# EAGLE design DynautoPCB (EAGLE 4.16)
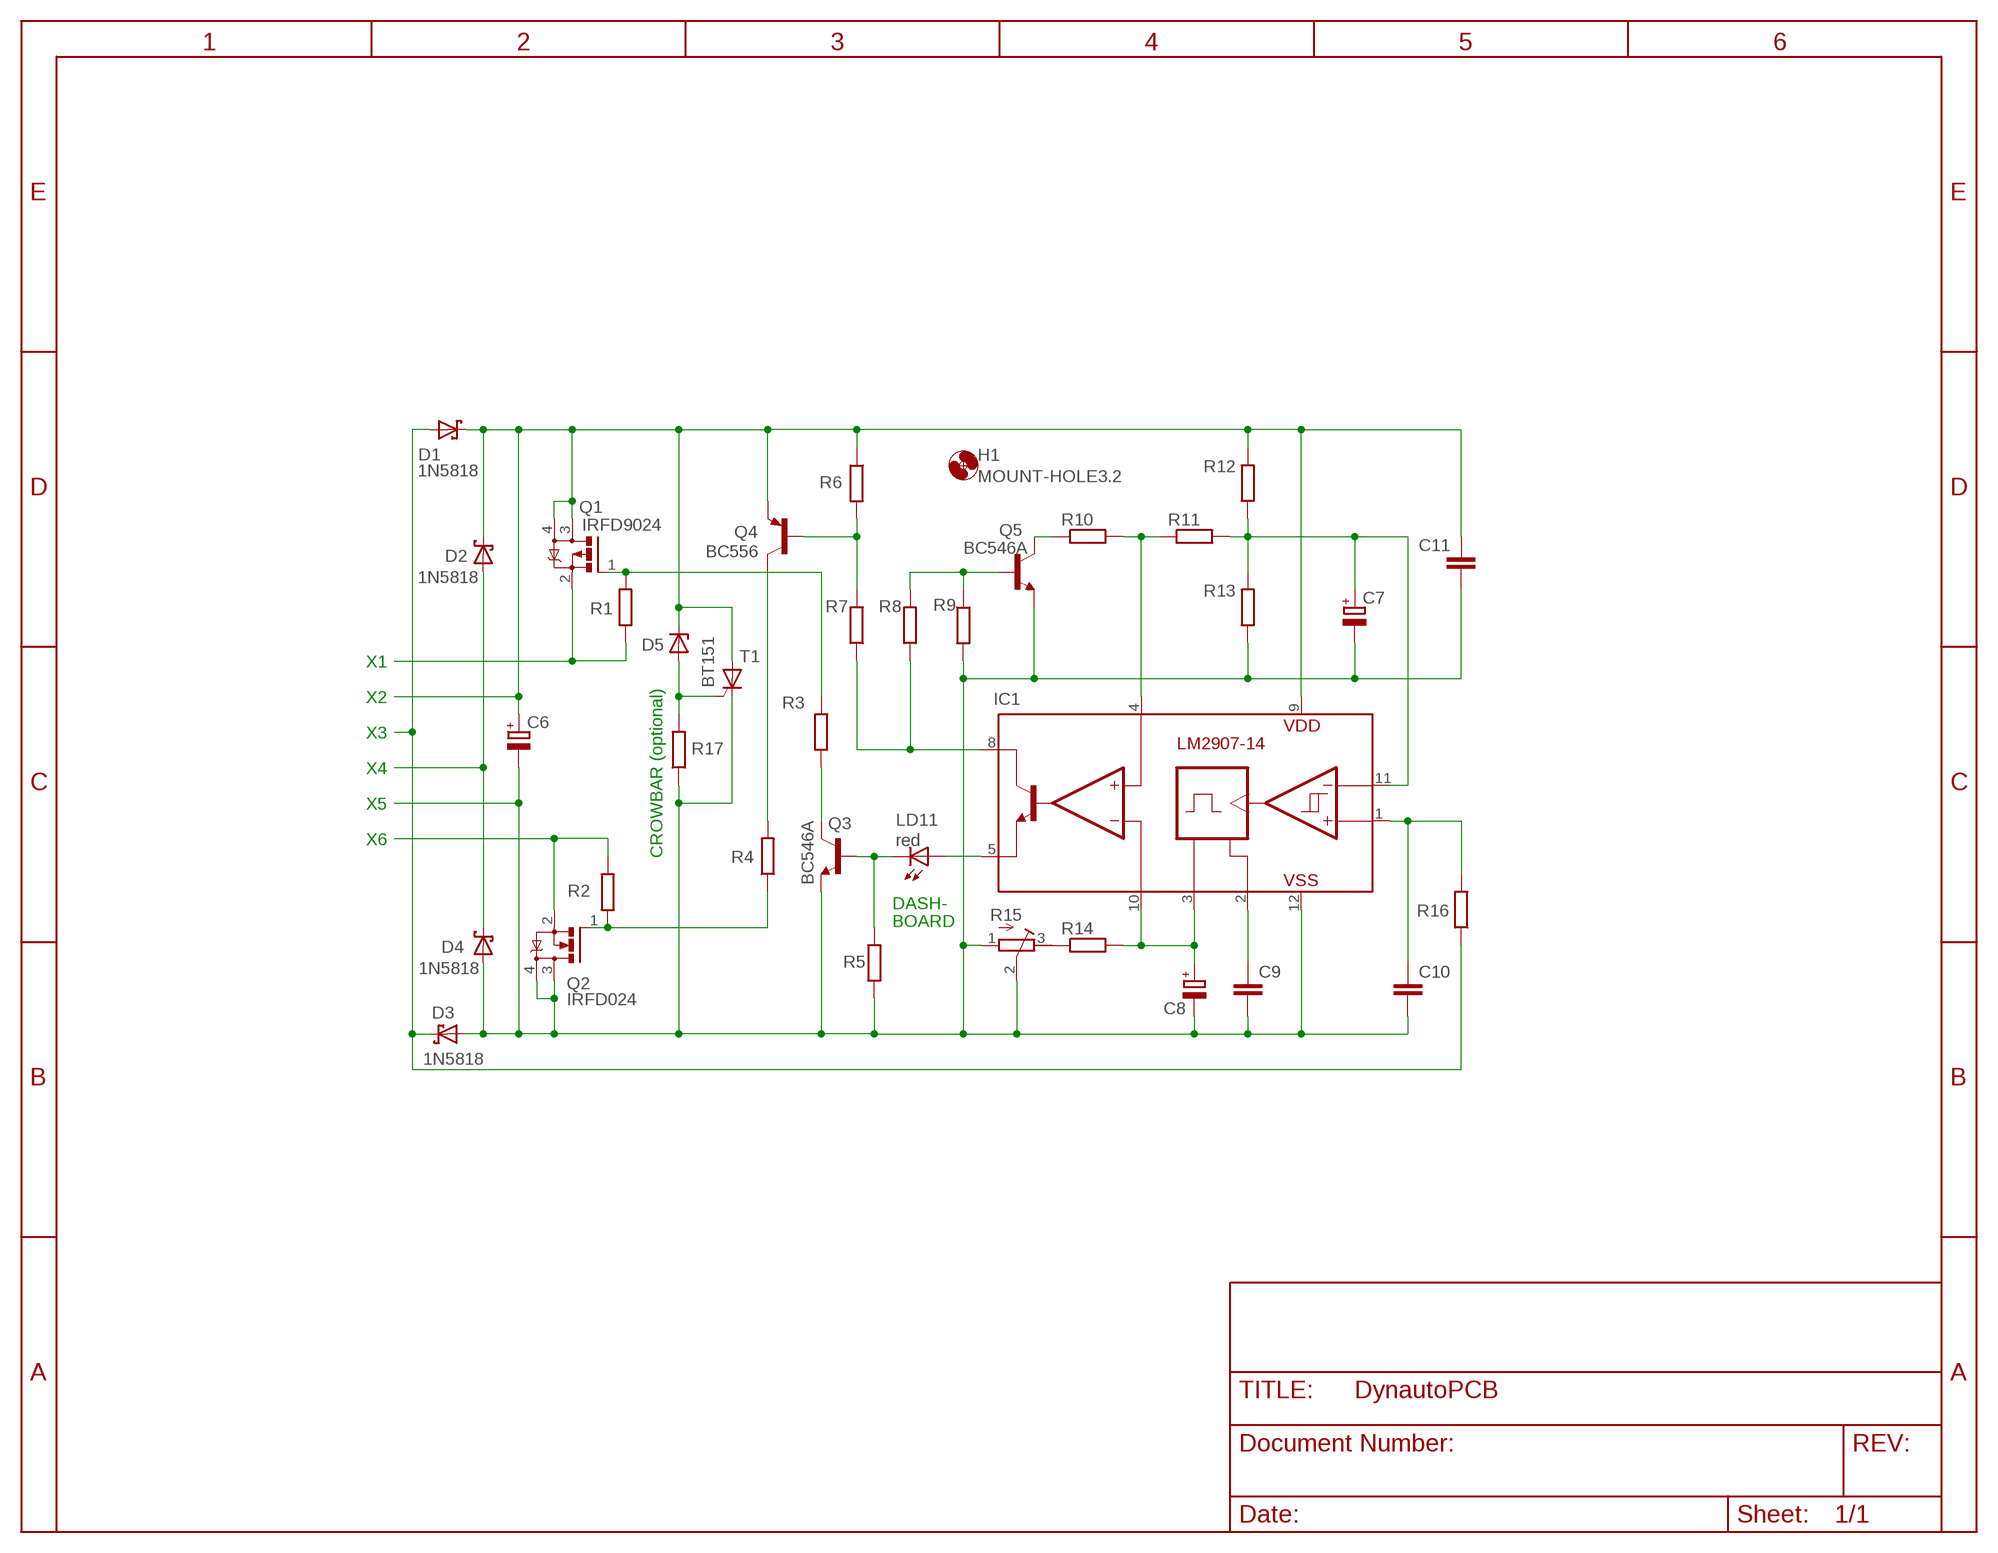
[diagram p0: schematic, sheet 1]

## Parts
C6  CPOL-EUTT5D2.5-10  [TT5D2.5-10]
C7  CPOL-EUE2.5-5  [E2,5-5]
C8  CPOL-EUE2.5-5  [E2,5-5]
C9  C-EU025_050-045X075  [C025_050-045X075]
C10  C-EU025_050-035X075  [C025_050-035X075]
C11  C-EU025_050-035X075  [C025_050-035X075]
D1  1N5818  1N5818H  [DO41-10]
D2  1N5818  1N5818H  [DO41-10]
D3  1N5818  1N5818H  [DO41-10]
D4  1N5818  1N5818H  [DO41-10]
D5  ZENER-DIODEDO34-7  [DO34Z7]
H1  MOUNT-HOLE3.2  [3,2]
IC1  LM2907-14N  [DIL14]
LD11  red  LEDV  [LED3MM]
Q1  IRFD9024  [DIL-8]
Q2  IRFD024  [DIL-8]
Q3  BC546A  [TO92-EBC]
Q4  BC556  [TO92-EBC]
Q5  BC546A  [TO92-EBC]
R1  R-EU_0204/2V  [0204V]
R2  R-EU_0204/2V  [0204V]
R3  R-EU_0204/2V  [0204V]
R4  R-EU_0204/2V  [0204V]
R5  R-EU_0204/2V  [0204V]
R6  R-EU_0204/2V  [0204V]
R7  R-EU_0207/10  [0207/10]
R8  R-EU_0204/2V  [0204V]
R9  R-EU_0204/2V  [0204V]
R10  R-EU_0204/2V  [0204V]
R11  R-EU_0204/2V  [0204V]
R12  R-EU_0204/2V  [0204V]
R13  R-EU_0204/2V  [0204V]
R14  R-EU_0204/2V  [0204V]
R15  R-TRIMM74W  [RTRIM74W]
R16  R-EU_0207/10  [0207/10]
R17  R-EU_0207/10  [0207/10]
T1  BT151  [TO220CL]

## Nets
N$1: D1.A D3.C R16.1
N$2: Q1.2(S) R1.1
N$3: C6.- C7.- C8.- C9.2 C10.2 C11.2 D3.A D4.A IC1.12 Q2.3(D1) Q2.4(D2) Q3.E Q5.E R5.1 R9.2 R13.1 R15.1(E) R15.2(S) R17.1 T1.C
N$4: Q1.1(G) R1.2 R3.1
N$5: C8.+ IC1.3 IC1.10 R14.2
N$6: Q2.1(G) R2.2 R4.1
N$7: C6.+ C11.1 D1.C D2.C D5.C IC1.9 Q1.3(D1) Q1.4(D2) Q4.E R6.1 R12.2 T1.A
N$8: C9.1 IC1.2
N$9: LD11.K(C) Q3.B R5.2
N$10: Q2.2(S) R2.1
N$11: IC1.8 R7.1 R8.1
N$12: Q4.B R6.2 R7.2
N$13: D5.A R17.2 T1.G
N$14: Q5.C R10.1
N$15: D2.A D4.C
N$16: IC1.5 LD11.A
N$17: IC1.4 R10.2 R11.1
N$18: R14.1 R15.3(A)
N$19: C7.+ IC1.11 R11.2 R12.1 R13.2
N$20: C10.1 IC1.1 R16.2
N$21: Q3.C R3.2
N$22: Q4.C R4.2
Q333: Q5.B R8.2 R9.1

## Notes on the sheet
- X1
- X2
- X3
- X4
- X5
- X6
- CROWBAR (optional)
- DASH-
- BOARD

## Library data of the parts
C6-C8 = BikeLight:CPOL-EU: POLARIZED CAPACITOR, European symbol
C9-C11 = BikeLight:C-EU: CAPACITOR, European symbol
D1-D4 = BikeLight:1N5818: DIODE
D5 = BikeLight:ZENER-DIODE: Z-Diode
H1 = BikeLight:MOUNT-HOLE: MOUNTING HOLE with drill center marker
IC1 = BikeLight:LM2907-14: Frequency to Voltage Converter
LD11 = BikeLight:LED: PLH006 Series SMD LED SOT23
Q1 = BikeLight:IRFD9024
Q2 = BikeLight:IRFD024
Q3 Q5 = BikeLight:BC546*: NPN Transistor
Q4 = BikeLight:BC556*: PNP Transistror
R1-R14 R16 R17 = BikeLight:R-EU_: RESISTOR, European symbol
R15 = BikeLight:R-TRIMM: Trimm resistor
T1 = BikeLight:BT151: THYRISTOR

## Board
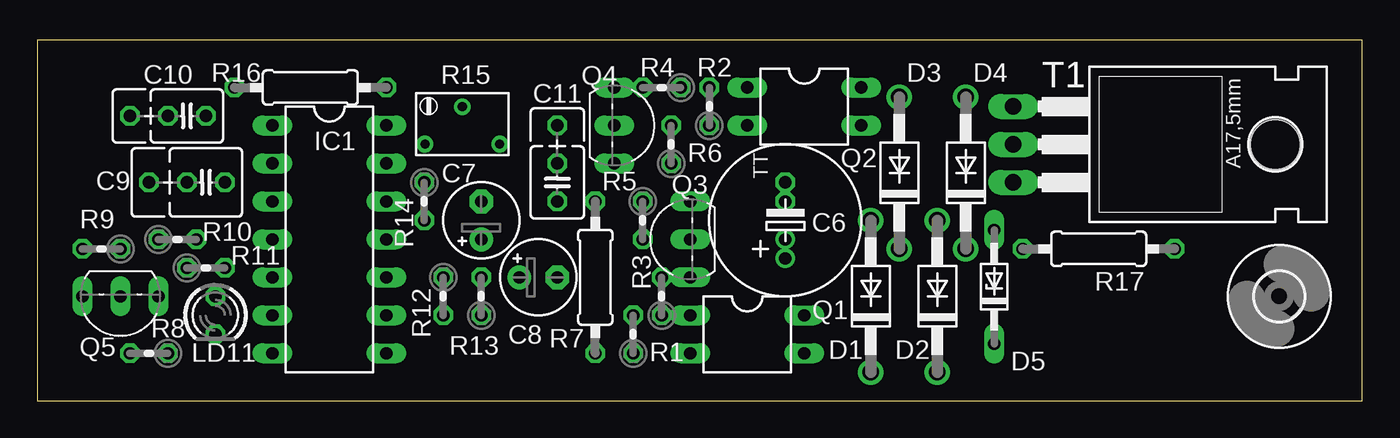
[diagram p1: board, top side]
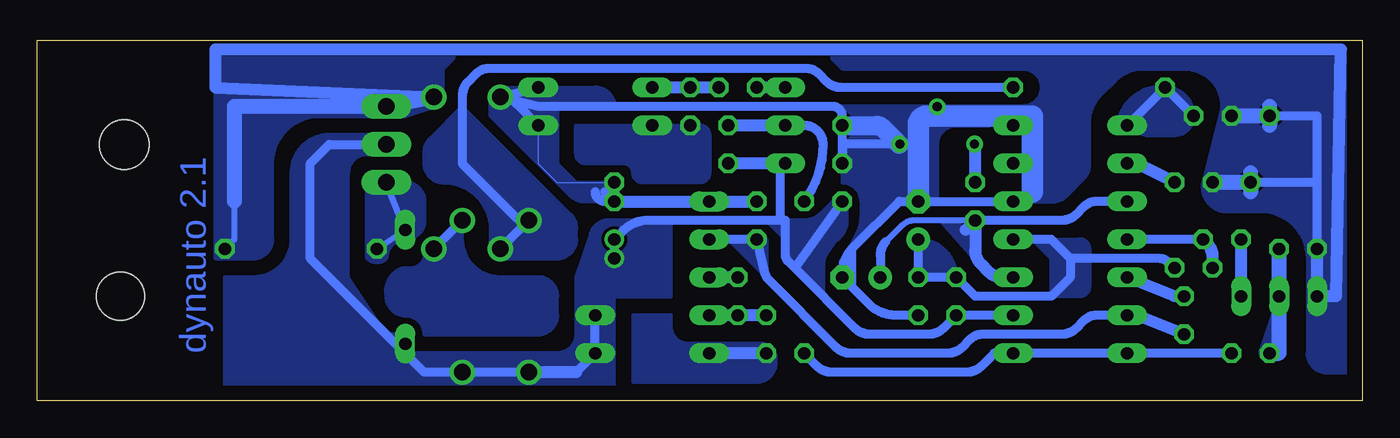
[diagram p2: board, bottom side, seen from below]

Size 88.57 x 24.12 mm. Coordinates in mm from the lower left corner, seen from the top.
Outline: 0,0 88.57,0 88.57,24.12 0,24.12 0,0
Copper layers (1*16): Top 0.035mm / dielectric 1.5mm / Bottom 0.035mm
Design rules "default": minimum track width 10mil, minimum drill 24mil, track to track 8mil, track to pad 8mil, pad to pad 8mil, via to via 8mil, smd to smd 8mil, copper to edge 40mil, drill to drill 8mil, minimum pad ring 10mil, minimum via ring 8mil, stop-mask expansion 4mil, vias tented up to drill 0mil, thermal gap 10mil

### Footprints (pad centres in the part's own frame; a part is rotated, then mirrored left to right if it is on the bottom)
TT5D2.5-10 = drill 0.813 round: + -2.54,0; +1 -1.27,0 | drill 0.813 octagon: - 2.54,0; -1 1.27,0
E2,5-5 = drill 0.813 pad 1.6 round: + -1.27,0 | drill 0.813 pad 1.6 octagon: - 1.27,0
C025_050-045X075 = drill 0.813 octagon: 1 -1.27,0; 2 1.27,0; 3 3.81,0
C025_050-035X075 = drill 0.813 octagon: 1 -1.27,0; 2 1.27,0; 3 3.81,0
DO41-10 = drill 1.118 round: A 5.08,0; C -5.08,0
DO34Z7 = drill 0.813 long: A 3.81,0; C -3.81,0
3,2 = hole 3.2: 0,0
DIL14 = drill 0.813 long: 1 -7.62,-3.81; 2 -5.08,-3.81; 3 -2.54,-3.81; 4 0,-3.81; 5 2.54,-3.81; 6 5.08,-3.81; 7 7.62,-3.81; 8 7.62,3.81; 9 5.08,3.81; 10 2.54,3.81; 11 0,3.81; 12 -2.54,3.81; 13 -5.08,3.81; 14 -7.62,3.81
LED3MM = drill 0.813 octagon: A -1.27,0; K 1.27,0
DIL-8 = drill 0.813 long: 1 -1.27,-3.81; 2 1.27,-3.81; 3 1.27,3.81; 4 -1.27,3.81
TO92-EBC = drill 0.813 long: B 0,-1.27; C -2.54,-1.27; E 2.54,-1.27
0204V = drill 0.813 octagon: 1 -1.27,0; 2 1.27,0
0207/10 = drill 0.813 octagon: 1 -5.08,0; 2 5.08,0
RTRIM74W = drill 0.61 round: 1 -1.25,-2.5; 2 1.25,0; 3 -1.25,2.5
TO220CL = drill 1.118 long: A 0,-6.35; C -2.54,-6.35; G 2.54,-6.35 | hole 3.302: 0,11.176

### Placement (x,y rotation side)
C6  50,12.06 90 top
C7  29.68,12.06 90 top
C8  33.49,8.25 0 top
C9  11.27,14.6 180 top
C10  10,19.04 180 top
C11  34.76,14.6 90 top
D1  55.71,6.98 90 top
D2  60.16,6.98 90 top
D3  57.62,15.24 90 top
D4  62.06,15.24 90 top
D5  63.97,7.62 90 top
H1  83.02,6.98 0 top
IC1  19.52,10.79 270 top
LD11  11.9,5.71 270 top
Q1  47.46,4.44 270 top
Q2  51.27,19.68 270 top
Q3  42.38,10.79 90 top
Q4  39.84,18.41 270 top
Q5  5.55,5.71 180 top
R1  39.84,4.44 90 top
R2  44.92,19.68 90 top
R3  41.74,6.98 90 top
R4  41.74,20.95 180 top
R5  40.48,12.06 270 top
R6  42.38,17.14 90 top
R7  37.3,8.25 90 top
R8  7.46,3.17 180 top
R9  4.28,10.16 180 top
R10  9.36,10.79 0 top
R11  11.27,8.89 0 top
R12  27.14,6.98 270 top
R13  29.68,6.98 90 top
R14  25.87,13.33 270 top
R15  28.41,18.41 90 top
R16  18.25,20.95 180 top
R17  70.95,10.16 180 top
T1  71.59,17.14 270 top

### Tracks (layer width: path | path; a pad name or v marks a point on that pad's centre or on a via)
N$1
  Bottom 0.61: D3.C D1.A 56.35,12.06 60.16,15.87 60.16,20.42 arc45 59.79,21.32 59.26,21.85 arc45 58.36,22.22 37.19,22.22 arc45 36.29,21.85 35.77,21.32 arc-45 34.87,20.95 R16.1
  pour Bottom (no thermals): 61.43,14.6 arc90 58.25,11.43 58.25,10.79 arc-53 57.62,9.52 53.81,9.52 arc-90 52.54,10.79 52.54,11.53 arc-45 52.91,12.43 60.16,19.68 62.33,17.51 arc-45 62.7,16.61 62.7,15.87 arc-90
N$2
  Bottom 0.813: R1.1 Q1.2
  pour Bottom (no thermals): 46.19,5.71 48.73,5.71 48.73,1.27 40.48,1.27 arc-90 39.2,2.54 arc-90 40.16,3.8 44.92,3.8 arc90 46.19,4.76
N$3
  Bottom 0: C6.- 53.81,14.6 55.08,15.87 Q2.3
  Bottom 0.406: 75.4,13.33 75.4,10.79 R17.1
  Bottom 0.61: Q3.E R5.1 | R15.1 34.74,17.16 34.76,17.14 C11.2 34.76,18.41 34.76,19.04 arc-90 35.39,19.68 55.08,19.68 D3.A | C6.- 50,13.33 | IC1.12 C7.- 30.95,13.33 34.03,10.25 arc-45 34.76,8.48 C8.- 34.12,7.62 | D3.A Q2.4 | 50,13.33 50.63,13.33 arc90 51.27,13.97 | 50,13.33 50.63,13.97 | 3.01,14.6 7.46,14.6 | 6.18,19.04 3.01,19.04 3.01,14.6 | R9.2 3.01,14.6 | 34.12,7.62 32.95,6.44 arc-45 31.18,5.71 R13.1 | 34.12,7.62 34.12,10.16 | D3.A arc45 56.54,19.87 Q2.3
  Bottom 0.813: 50,13.33 Q3.E R5.1 | D4.A 76.67,20.95 76.67,23.49 1.42,23.49 1.74,6.98 Q5.E R9.2
  Bottom 1.016: D4.A T1.C 75.4,19.68 75.4,13.33 | 6.18,19.04 6.18,18.41 | 6.18,19.04 6.18,19.68 | 7.46,14.6 7.46,13.97 | 7.46,14.6 7.46,15.24 | 7.46,14.6 C9.2 | 6.18,19.04 C10.2
  Bottom 1.27: 30.95,17.14 32.03,18.22 arc-45 32.48,18.41 34.76,18.41
  Bottom 1.422: C7.- 29.68,18.41 arc90 29.04,19.04 22.06,19.04 22.06,13.97
  pour Bottom (no thermals): 50,14.6 50,13.33 52.01,13.33 arc45 52.91,13.7 58.25,19.04 58.25,20.31 57.62,20.95 51.27,20.95 arc90 50,19.68 53.81,19.68 53.81,15.87 52.54,14.6
  pour Bottom (no thermals): 76.67,9.52 74.13,9.52 arc-90 72.86,10.79 72.86,15.87 arc90 69.69,19.04 70.32,19.04 63.97,19.04 62.06,19.68 61.43,20.95 61.43,22.22 60.16,23.49 76.67,23.49
  pour Bottom (no thermals): 36.03,23.49 34.76,22.22 22.7,22.22 arc90 21.42,20.95 arc90 22.7,19.68 34.76,19.68 34.76,14.6 arc90 33.49,13.33 33.49,12.33 arc27 33.75,11.21 34.44,9.84 30.95,13.33 28.41,13.33 28.41,17.14 arc90 27.14,18.41 22.06,18.41 22.06,13.33 20.68,13.33 arc-45 19.78,13.7 18.62,14.86 arc-45 18.25,15.76 18.25,18.64 arc45 17.52,20.41 16.44,21.49 arc45 14.67,22.22 11.9,22.22 arc90 9.36,19.68 10.63,14.6 arc-90 9.36,12.7 6.82,12.7 arc90 3.64,9.52 3.64,3.17 arc-90 2.38,1.9 0.47,1.9 0.47,23.49
N$4
  Bottom 0.813: R1.2 R3.1 Q1.1
N$5
  Bottom 0.406: R14.2 29.9,12.06 arc-45 30.8,11.69 31.85,10.64
  Bottom 0.61: IC1.3 17.72,13.33 arc-45 18.62,12.96 19.15,12.43 arc45 20.05,12.06 R14.2 | 31.85,10.64 arc-45 32.22,9.74 C8.+
  Bottom 0.813: IC1.10 24.07,8.25 arc45 24.97,8.62 25.5,9.15 arc45 25.87,10.05 R14.2 26.5,11.43
  pour Bottom: 25.87,9.52 28.09,12.06 25.87,12.06
N$6
  Bottom 0.813: Q2.1 R2.2 R4.1
N$7
  Bottom 0.61: D1.C D2.C 62.7,1.9 64.61,3.8 | 52.54,1.9 Q1.3 Q1.4 | IC1.9 R12.2 28.04,4.81 arc45 28.94,4.44 32.96,4.44 arc45 33.86,4.81 37.94,8.89 | 64.61,3.8 70.32,9.52 70.32,15.87 69.05,17.14 T1.A | 64.61,3.8 D5.C | 37.94,8.89 38.38,9.33 arc45 38.57,9.78 38.57,12.06 38.89,12.06 | 37.94,8.89 C11.1 | C6.+ 50,10.79 49.46,11.33 arc45 47.69,12.06 38.89,12.06 | Q4.E 38.89,15.87 38.89,12.06
  Bottom 0.813: 52.54,1.9 D1.C | Q4.E R6.1
  pour Bottom (no thermals): 39.84,12.06 38.57,10.79 38.57,9.52 36.03,6.98 36.03,9.1 arc36 35.78,9.86 35.13,10.74 arc-45 34.44,11.95 34.44,13.33 35.39,13.33 36.29,12.43 arc45 37.19,12.06
  pour Bottom (no thermals): 76.03,8.25 76.03,0.63 50,0.63 50,6.98 46.19,6.98 46.19,12.06 50.35,12.06 arc-72 51.56,11.19 52.54,8.25 52.54,4.44 arc90 53.81,3.17 63.97,3.17 63.97,4.44 65.24,4.44 67.78,8.25 67.78,15.24 arc90 66.51,16.5 65.88,16.5 65.24,17.14 65.88,17.77 69.05,17.77 arc-90 71.59,15.24 71.59,10.79 arc90 74.13,8.25
N$8
  Bottom 0.813: C9.1 15.08,15.87 arc-53 IC1.2
N$9
  Bottom 0.61: 15.08,5.71 17.72,5.71 arc-45 18.62,5.34 19.15,4.81 arc45 20.05,4.44 25.34,4.44 arc-45 26.24,4.07 26.77,3.54 arc45 27.67,3.17 34.23,3.17 arc45 35.13,3.54 39.72,8.13 arc31 39.88,8.42 R5.2 Q3.B
  Bottom 0.813: LD11.K 15.08,5.71
  pour Bottom (no thermals): 39.84,8.25 42.38,10.79 39.84,10.79
N$10
  pour Bottom (no thermals): 51.91,15.87 arc90 52.54,16.5 52.54,18.41 44.28,18.41 arc90 43.65,17.77 43.65,15.24 arc90 44.28,14.6 48.09,14.6 arc90 48.73,15.24 arc-90 49.37,15.87
N$11
  Bottom 0.61: R8.1 IC1.8 24.6,3.17 25.5,2.27 arc45 26.4,1.9 35.5,1.9 arc45 36.4,2.27 R7.1
N$12
  Bottom 0.61: Q4.B 37.3,18.41 arc90 36.03,17.14 arc37 R7.2
  Bottom 0.813: Q4.B R6.2
N$13
  Bottom 0.406: T1.G D5.A R17.2
  pour Bottom (no thermals): 63.97,14.6 arc90 62.7,13.33 62.7,12.06 arc90 63.97,10.79 arc-90 65.24,9.52 arc90 66.51,9.52 66.51,14.6
N$14
  Bottom 0.813: Q5.C R10.1
N$15
  Bottom 0.61: D4.C D2.A
  pour Bottom (isolate 0.305, no thermals): 57.62,8.25 arc90 60.16,10.79 60.16,12.06 62.7,9.52 arc90 63.97,8.89 arc-90 65.24,6.98 arc-90 63.97,5.71 arc90 62.7,4.44 55.08,4.44 arc-90 53.81,5.71 53.81,6.98 arc-90 55.08,8.25
N$16
  Bottom 0.813: LD11.A 12.54,6.98 IC1.5
N$17
  Bottom 0.61: R10.2 IC1.4
  Bottom 0.813: R11.1 10,9.63 arc-45 10.37,10.53 R10.2
N$18
  Bottom 0.61: 25.87,17.14 R15.3
  Bottom 0.813: R14.1 25.87,17.14
N$19
  Bottom 0.61: IC1.11 20.79,10.79 19.52,9.52 | R11.2 12.8,9.15 arc-45 13.7,9.52 19.52,9.52 | 19.52,9.52 19.52,8.25 20.79,6.98 25.87,6.98 R12.1 R13.2 C7.+
  pour Bottom (no thermals): 27.14,8.25 arc-90 29.68,10.79 29.68,8.25
  pour Bottom (no thermals): 22.06,10.79 18.88,10.79 arc90 18.25,10.16 18.25,7.62 arc90 18.88,6.98 20.79,6.98 20.79,9.52
N$20
  Bottom 0.61: IC1.1 R16.2 C10.1
  pour Bottom (isolate 0.813, no thermals): 11.27,19.04 arc-90 13.17,20.95 arc-90 16.34,18.41 14.44,17.77 12.54,17.77 arc-90
N$21
  Bottom 0.813: R3.2 Q3.C
N$22
  Bottom 0.813: Q4.C R4.2
Q333
  Bottom 1.016: R8.2 5.55,3.17 Q5.B R9.1
  pour Bottom (isolate 0.813, no thermals): 6.82,3.17 5.55,6.98 5.55,3.17

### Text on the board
Bottom: dynauto 2.1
